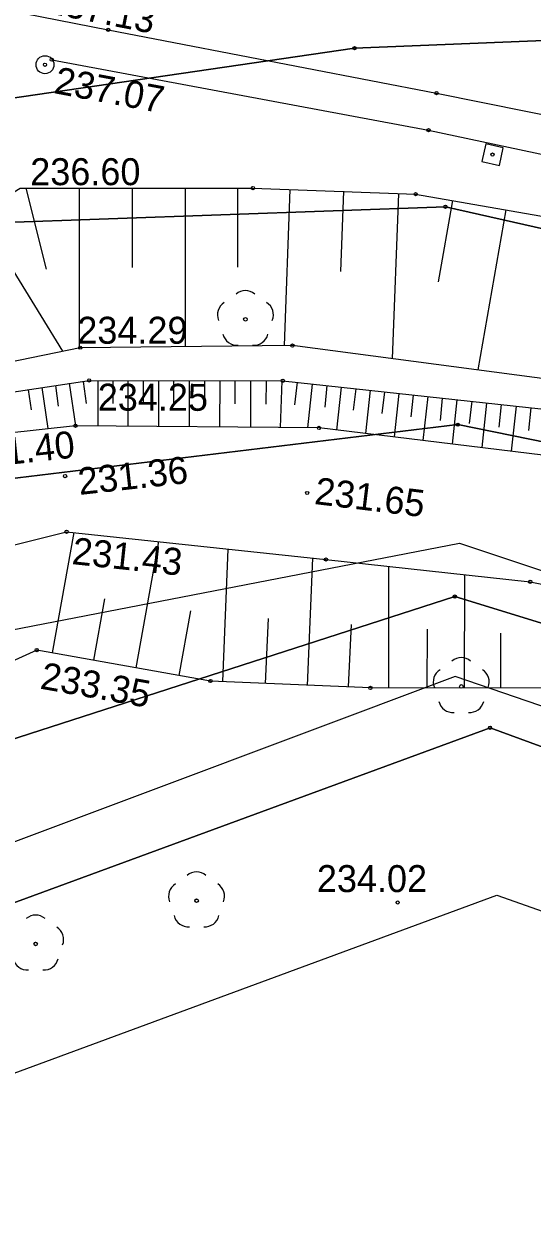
# Model space of a CAD drawing. Extents: x 6596400 to 6597200, y 5539751 to 5540251.
# Drawn here: x 6596774.08 to 6596788.23, y 5540046.04 to 5540079.28 of the extents above; entities that cross this region are included whole.
import ezdxf

# ---------------------------------------------------------------- set-up
doc = ezdxf.new("R2010")
doc.units = 0
for name, color, linetype in [('000 Inne (niezydentyfikowane)', 7, 'Continuous'), ('140-Punkty robocze', 7, 'Continuous'), ('203-punkt graniczny', 7, 'Continuous'), ('217-kontur klasyfikacyjny', 7, 'Continuous'), ('218-kontur użytku gruntowego', 7, 'Continuous'), ('219-działka ewidencyjna', 7, 'Continuous'), ('bariera ochronna', 7, 'Continuous'), ('drzewo liściaste', 7, 'Continuous'), ('jezdnia', 7, 'Continuous'), ('Linia obszaru zagospodarowania terenu', 7, 'Continuous'), ('pikieta sztuczna', 7, 'Continuous'), ('pikieta sztuczna-Atr2', 7, 'Continuous'), ('rów melioracyjny (poligon)', 7, 'Continuous'), ('skarpa umocniona', 7, 'Continuous'), ('właz do komory lub kanału - kwadratowy', 7, 'Continuous'), ('właz do komory lub kanału - okrągły', 7, 'Continuous'), ('Zakres', 7, 'Continuous')]:
    doc.layers.add(name, color=color, linetype=linetype)

# ---------------------------------------------------------------- blocks, each defined once
blk = doc.blocks.new('203')
blk.add_circle((0, 0), 0.045)
blk = doc.blocks.new('OP021')
blk.add_circle((0, 0), 0.05)
for centre, start, end in [((0, 0.4), 49.272, 130.728), ((-0.38, 0.124), 121.308, 202.548), ((0.38, 0.124), 337.452, 58.692), ((-0.235, -0.324), 193.221, 274.871), ((0.235, -0.324), 265.129, 346.779)]:
    blk.add_arc(centre, 0.4, start, end)
blk = doc.blocks.new('US22A')
blk.add_lwpolyline([(-0.25, -0.25), (0.25, -0.25), (0.25, 0.25), (-0.25, 0.25)], close=True)
blk = doc.blocks.new('US22')
blk.add_circle((0, 0), 0.25)
blk = doc.blocks.new('PW01')
blk.add_circle((0, 0), 0.045)
blk = doc.blocks.new('PIKIETA')
blk.add_circle((0, 0), 0.045)

msp = doc.modelspace()

# ---------------------------------------------------------------- linework, layer by layer
at = {"layer": '000 Inne (niezydentyfikowane)'}
for p, q in [((6596774.14, 5540074.71), (6596774.7, 5540072.45)), ((6596775.62, 5540074.71), (6596775.62, 5540070.26)), ((6596777.1, 5540074.71), (6596777.1, 5540072.5)), ((6596778.57, 5540074.71), (6596778.57, 5540070.3)), ((6596780.03, 5540074.71), (6596780.03, 5540072.51)), ((6596781.49, 5540074.67), (6596781.33, 5540070.33)), ((6596782.98, 5540074.62), (6596782.9, 5540072.39)), ((6596784.51, 5540074.56), (6596784.34, 5540069.96)), ((6596786.02, 5540074.36), (6596785.62, 5540072.1)), ((6596772.81, 5540073.99), (6596775.16, 5540070.17)), ((6596787.5, 5540074.1), (6596786.72, 5540069.65)), ((6596775.73, 5540069.33), (6596775.82, 5540068.72)), ((6596776.14, 5540069.36), (6596776.14, 5540068.09)), ((6596776.56, 5540069.36), (6596776.56, 5540068.72)), ((6596776.98, 5540069.36), (6596776.98, 5540068.09)), ((6596777.4, 5540069.36), (6596777.4, 5540068.72)), ((6596777.83, 5540069.36), (6596777.83, 5540068.08)), ((6596778.25, 5540069.36), (6596778.25, 5540068.72)), ((6596778.68, 5540069.35), (6596778.68, 5540068.07)), ((6596779.11, 5540069.35), (6596779.11, 5540068.71)), ((6596779.54, 5540069.35), (6596779.53, 5540068.06)), ((6596779.96, 5540069.35), (6596779.96, 5540068.71)), ((6596780.39, 5540069.35), (6596780.39, 5540068.06)), ((6596780.83, 5540069.35), (6596780.82, 5540068.7)), ((6596781.26, 5540069.35), (6596781.22, 5540068.05)), ((6596781.69, 5540069.31), (6596781.62, 5540068.68)), ((6596774.2, 5540069.1), (6596774.29, 5540068.54)), ((6596774.58, 5540069.16), (6596774.75, 5540068.02)), ((6596774.96, 5540069.22), (6596775.04, 5540068.64)), ((6596775.34, 5540069.28), (6596775.52, 5540068.1)), ((6596782.11, 5540069.26), (6596781.98, 5540068.04)), ((6596782.52, 5540069.22), (6596782.46, 5540068.62)), ((6596782.92, 5540069.17), (6596782.79, 5540067.98)), ((6596783.32, 5540069.13), (6596783.25, 5540068.53)), ((6596783.72, 5540069.09), (6596783.59, 5540067.88)), ((6596784.12, 5540069.04), (6596784.05, 5540068.44)), ((6596784.52, 5540069), (6596784.39, 5540067.79)), ((6596784.92, 5540068.95), (6596784.86, 5540068.35)), ((6596785.33, 5540068.91), (6596785.19, 5540067.69)), ((6596785.73, 5540068.87), (6596785.67, 5540068.25)), ((6596786.14, 5540068.82), (6596786.01, 5540067.59)), ((6596786.55, 5540068.78), (6596786.48, 5540068.16)), ((6596786.96, 5540068.73), (6596786.83, 5540067.49)), ((6596787.37, 5540068.69), (6596787.31, 5540068.06)), ((6596787.79, 5540068.64), (6596787.65, 5540067.39)), ((6596788.2, 5540068.6), (6596788.13, 5540067.97)), ((6596774.88, 5540061.78), (6596775.48, 5540065.13)), ((6596777.21, 5540061.37), (6596777.84, 5540064.88)), ((6596779.62, 5540060.99), (6596779.77, 5540064.67)), ((6596781.98, 5540060.88), (6596782.13, 5540064.42)), ((6596784.24, 5540060.81), (6596784.24, 5540064.19)), ((6596786.35, 5540060.8), (6596786.36, 5540063.96)), ((6596776.03, 5540061.58), (6596776.34, 5540063.29)), ((6596778.41, 5540061.15), (6596778.73, 5540062.95)), ((6596780.81, 5540060.93), (6596780.89, 5540062.74)), ((6596783.12, 5540060.84), (6596783.2, 5540062.57)), ((6596785.31, 5540060.81), (6596785.32, 5540062.44)), ((6596787.36, 5540060.8), (6596787.36, 5540062.33))]:
    msp.add_line(p, q, dxfattribs=at)
at = {"layer": '217-kontur klasyfikacyjny'}
for points in [[(6596787.06, 5540059.7), (6596753.05, 5540047.22)], [(6596806.51, 5540052.58), (6596787.06, 5540059.7)]]:
    msp.add_lwpolyline(points, dxfattribs=at)
at = {"layer": '218-kontur użytku gruntowego'}
for points in [[(6596783.29, 5540078.6), (6596799.12, 5540079.24)], [(6596799.12, 5540079.24), (6596783.29, 5540078.6)], [(6596753.12, 5540074.2), (6596783.29, 5540078.6)], [(6596783.29, 5540078.6), (6596753.12, 5540074.2)], [(6596785.82, 5540074.19), (6596773.3, 5540073.74)], [(6596773.3, 5540073.74), (6596785.82, 5540074.19)], [(6596806.19, 5540069.6), (6596785.82, 5540074.19)], [(6596785.82, 5540074.19), (6596806.19, 5540069.6)], [(6596753.08, 5540064.13), (6596786.16, 5540068.13)], [(6596786.16, 5540068.13), (6596753.08, 5540064.13)], [(6596786.16, 5540068.13), (6596805.25, 5540064.25)], [(6596805.25, 5540064.25), (6596786.16, 5540068.13)], [(6596786.08, 5540063.35), (6596749.37, 5540051.51)], [(6596749.37, 5540051.51), (6596786.08, 5540063.35)], [(6596807.71, 5540056.7), (6596786.08, 5540063.35)], [(6596786.08, 5540063.35), (6596807.71, 5540056.7)], [(6596787.06, 5540059.7), (6596753.05, 5540047.22)], [(6596753.05, 5540047.22), (6596787.06, 5540059.7)], [(6596806.51, 5540052.58), (6596787.06, 5540059.7)], [(6596787.06, 5540059.7), (6596806.51, 5540052.58)]]:
    msp.add_lwpolyline(points, dxfattribs=at)
at = {"layer": '219-działka ewidencyjna'}
for points in [[(6596783.29, 5540078.6), (6596799.12, 5540079.24)], [(6596753.12, 5540074.2), (6596783.29, 5540078.6)], [(6596773.3, 5540073.74), (6596785.82, 5540074.19)], [(6596806.19, 5540069.6), (6596785.82, 5540074.19)], [(6596753.08, 5540064.13), (6596786.16, 5540068.13)], [(6596805.25, 5540064.25), (6596786.16, 5540068.13)], [(6596749.37, 5540051.51), (6596786.08, 5540063.35)], [(6596807.71, 5540056.7), (6596786.08, 5540063.35)], [(6596753.05, 5540047.22), (6596787.06, 5540059.7)], [(6596806.51, 5540052.58), (6596787.06, 5540059.7)]]:
    msp.add_lwpolyline(points, dxfattribs=at)
at = {"layer": 'bariera ochronna'}
msp.add_lwpolyline([(6596774.86, 5540078.28), (6596785.35, 5540076.32), (6596790.54, 5540075.22), (6596793.53, 5540074.48), (6596795.64, 5540073.93), (6596798.3, 5540073.09), (6596802.06, 5540071.69), (6596807.84, 5540069.06), (6596812.67, 5540066.17), (6596814.81, 5540064.78), (6596821.33, 5540060.18), (6596825.095, 5540057.67)], dxfattribs=at)
at = {"layer": 'jezdnia'}
msp.add_lwpolyline([(6596748.72, 5540084.9), (6596758.31, 5540082.61), (6596767.09, 5540080.95), (6596776.43, 5540079.11), (6596785.57, 5540077.35), (6596790.64, 5540076.33), (6596793.76, 5540075.4), (6596796, 5540074.75), (6596799.11, 5540073.89), (6596802.37, 5540072.55), (6596804.34, 5540071.72), (6596806.42, 5540070.73), (6596808.2, 5540069.72), (6596810.28, 5540068.61), (6596812.76, 5540067.19), (6596815.5, 5540065.85), (6596818.95, 5540063.45), (6596822.11, 5540061.14), (6596825.559, 5540058.298)], dxfattribs=at)
at = {"layer": 'Linia obszaru zagospodarowania terenu'}
for points in [[(6596720.263, 5540058.387), (6596728.96, 5540057.84), (6596731.45, 5540057.76), (6596731.02, 5540064.64), (6596745.49, 5540064.58), (6596746.99, 5540056.99), (6596772.84, 5540062.25), (6596786.21, 5540064.83), (6596807.99, 5540057.58), (6596818.837, 5540049.192)], [(6596816.371, 5540045.853), (6596805.78, 5540054.39), (6596786.09, 5540061.13), (6596752.3, 5540048.46), (6596750.16, 5540045.43), (6596750.4, 5540037.69), (6596745.15, 5540037.73), (6596747.098, 5540030.366)]]:
    msp.add_lwpolyline(points, dxfattribs=at)
at = {"layer": 'rów melioracyjny (poligon)'}
for points in [[(6596820.208, 5540051.05), (6596817.24, 5540053.08), (6596812.31, 5540056.77), (6596808.36, 5540059.4), (6596802.55, 5540062.58), (6596795.13, 5540065.25), (6596788.99, 5540067.23), (6596782.3, 5540068.04), (6596775.52, 5540068.1), (6596768.51, 5540067.33), (6596764.82, 5540065.79), (6596761.35, 5540063.62), (6596758.63, 5540061.34), (6596754.58, 5540058.6), (6596752.07, 5540056.28), (6596746.75, 5540055.19), (6596741.65, 5540054.82), (6596742.01, 5540050.53), (6596747.46, 5540050.98), (6596751.88, 5540051.19), (6596756.01, 5540053.96), (6596757.53, 5540054.97), (6596761.73, 5540059.12)], [(6596761.73, 5540059.12), (6596765.87, 5540062.28), (6596769.5, 5540063.71), (6596775.27, 5540065.15), (6596782.49, 5540064.38), (6596788.18, 5540063.76), (6596793.92, 5540062.6), (6596807.97, 5540055.99), (6596815, 5540051.7), (6596818.611, 5540048.887)]]:
    msp.add_lwpolyline(points, dxfattribs=at)
at = {"layer": 'skarpa umocniona'}
msp.add_lwpolyline([(6596788.93, 5540069.36), (6596781.56, 5540070.33), (6596775.65, 5540070.27), (6596768.55, 5540068.81), (6596763.13, 5540067.04), (6596759.59, 5540065.28), (6596756.25, 5540062.4), (6596756.95, 5540064.41), (6596761.69, 5540068.02), (6596768.22, 5540071.18), (6596773.98, 5540074.71), (6596780.46, 5540074.71), (6596784.99, 5540074.54), (6596793.19, 5540073.11)], dxfattribs=at)
msp.add_lwpolyline([(6596788.93, 5540069.36), (6596781.56, 5540070.33), (6596775.65, 5540070.27), (6596768.55, 5540068.81), (6596763.13, 5540067.04), (6596759.59, 5540065.28), (6596756.25, 5540062.4), (6596756.95, 5540064.41), (6596761.69, 5540068.02), (6596768.22, 5540071.18), (6596773.98, 5540074.71), (6596780.46, 5540074.71), (6596784.99, 5540074.54), (6596793.19, 5540073.11)], dxfattribs=at)
for points in [[(6596781.29, 5540069.35), (6596788.9, 5540068.52), (6596795.46, 5540066.97), (6596804.46, 5540064.28), (6596817.35, 5540056.24), (6596821.61, 5540052.95), (6596820.21, 5540051.05), (6596817.24, 5540053.08), (6596812.31, 5540056.77), (6596808.36, 5540059.4), (6596802.55, 5540062.58), (6596795.13, 5540065.25), (6596788.99, 5540067.23), (6596782.3, 5540068.04), (6596775.52, 5540068.1), (6596768.51, 5540067.33), (6596764.82, 5540065.79), (6596761.35, 5540063.62), (6596758.63, 5540061.34), (6596756.16, 5540061.25), (6596760.14, 5540064.35), (6596763.69, 5540066.4), (6596768.63, 5540068.26), (6596775.9, 5540069.36)], [(6596781.29, 5540069.35), (6596788.9, 5540068.52), (6596795.46, 5540066.97), (6596804.46, 5540064.28), (6596817.35, 5540056.24), (6596821.61, 5540052.95), (6596820.21, 5540051.05), (6596817.24, 5540053.08), (6596812.31, 5540056.77), (6596808.36, 5540059.4), (6596802.55, 5540062.58), (6596795.13, 5540065.25), (6596788.99, 5540067.23), (6596782.3, 5540068.04), (6596775.52, 5540068.1), (6596768.51, 5540067.33), (6596764.82, 5540065.79), (6596761.35, 5540063.62), (6596758.63, 5540061.34), (6596756.16, 5540061.25), (6596760.14, 5540064.35), (6596763.69, 5540066.4), (6596768.63, 5540068.26), (6596775.9, 5540069.36)], [(6596782.49, 5540064.38), (6596788.18, 5540063.76), (6596793.92, 5540062.6), (6596807.97, 5540055.99), (6596815, 5540051.7), (6596818.61, 5540048.89), (6596817.09, 5540046.82), (6596813.04, 5540049.86), (6596807.32, 5540053.71), (6596801, 5540055.88), (6596793.16, 5540059.3), (6596788.6, 5540060.8), (6596783.73, 5540060.81), (6596779.28, 5540061), (6596774.44, 5540061.86), (6596770.5, 5540060.07), (6596764.63, 5540056.07), (6596761.73, 5540059.12), (6596765.87, 5540062.28), (6596769.5, 5540063.71), (6596775.27, 5540065.15)], [(6596782.49, 5540064.38), (6596788.18, 5540063.76), (6596793.92, 5540062.6), (6596807.97, 5540055.99), (6596815, 5540051.7), (6596818.61, 5540048.89), (6596817.09, 5540046.82), (6596813.04, 5540049.86), (6596807.32, 5540053.71), (6596801, 5540055.88), (6596793.16, 5540059.3), (6596788.6, 5540060.8), (6596783.73, 5540060.81), (6596779.28, 5540061), (6596774.44, 5540061.86), (6596770.5, 5540060.07), (6596764.63, 5540056.07), (6596761.73, 5540059.12), (6596765.87, 5540062.28), (6596769.5, 5540063.71), (6596775.27, 5540065.15)]]:
    msp.add_lwpolyline(points, close=True, dxfattribs=at)
at = {"layer": 'Zakres'}
msp.add_lwpolyline([(6596822.22, 5540097.5), (6596800.39, 5540105.4), (6596755.76, 5540121.45), (6596697.73, 5540120.74), (6596659.35, 5540133.92), (6596647.64, 5540109.28), (6596697.73, 5540077), (6596721.01, 5540057.77), (6596727.72, 5540045.95), (6596731.95, 5540033.61), (6596741.17, 5540031.18), (6596755.59, 5540029.2), (6596757.85, 5540044.22), (6596787.25, 5540055.04), (6596806.3, 5540048.33), (6596813.97, 5540042.6), (6596833.15, 5540068.58), (6596822.3, 5540077.75)], close=True, dxfattribs=at)

# ---------------------------------------------------------------- block references
at = {"layer": '140-Punkty robocze'}
for p in [(6596774.67, 5540078.14), (6596785.57, 5540077.35), (6596785.35, 5540076.32), (6596787.13, 5540075.64), (6596780.46, 5540074.71), (6596784.99, 5540074.54), (6596781.56, 5540070.33), (6596781.29, 5540069.35), (6596782.3, 5540068.04), (6596782.49, 5540064.38), (6596788.18, 5540063.76), (6596779.28, 5540061), (6596783.73, 5540060.81), (6596778.89, 5540054.89), (6596774.41, 5540053.69)]:
    msp.add_blockref('PIKIETA', p, dxfattribs=at)
at = {"layer": '203-punkt graniczny'}
for p in [(6596783.29, 5540078.6), (6596785.82, 5540074.19), (6596786.16, 5540068.13), (6596786.08, 5540063.35), (6596787.06, 5540059.7)]:
    msp.add_blockref('203', p, dxfattribs=at)
at = {"layer": 'drzewo liściaste'}
for p in [(6596780.25, 5540071.06), (6596786.26, 5540060.85), (6596778.89, 5540054.89), (6596774.41, 5540053.69)]:
    msp.add_blockref('OP021', p, dxfattribs=at)
at = {"layer": 'pikieta sztuczna'}
for p in [(6596776.43, 5540079.11), (6596774.86, 5540078.28), (6596775.65, 5540070.27), (6596775.9, 5540069.36), (6596775.52, 5540068.1), (6596775.23, 5540066.7), (6596781.97, 5540066.23), (6596775.27, 5540065.15), (6596774.44, 5540061.86), (6596784.49, 5540054.84)]:
    msp.add_blockref('PW01', p, dxfattribs=at)
at = {"layer": 'właz do komory lub kanału - kwadratowy', "rotation": 167.47099999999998}
msp.add_blockref('US22A', (6596787.13, 5540075.64), dxfattribs=at)
at = {"layer": 'właz do komory lub kanału - okrągły'}
msp.add_blockref('US22', (6596774.67, 5540078.14), dxfattribs=at)

# ---------------------------------------------------------------- texts
at = {"layer": 'pikieta sztuczna-Atr2'}
for s, rotation, p in [('237.13', 348.855, (6596774.645, 5540079.594)), ('237.07', 349.417, (6596774.892, 5540077.353)), ('234.25', 359.894, (6596776.139, 5540068.52)), ('231.40', 6.268, (6596772.482, 5540066.884)), ('231.36', 6.268, (6596775.632, 5540066.174)), ('231.65', 353.096, (6596782.15, 5540065.925)), ('231.43', 353.913, (6596775.4, 5540064.254)), ('233.35', 349.924, (6596774.509, 5540060.792))]:
    msp.add_text(s, height=0.75, rotation=rotation, dxfattribs=at).set_placement(p)
for s, p in [('236.60', (6596774.26, 5540074.79)), ('234.29', (6596775.57, 5540070.38)), ('234.02', (6596782.24, 5540055.13))]:
    msp.add_text(s, height=0.75, dxfattribs=at).set_placement(p)

doc.saveas('drawing.dxf')
